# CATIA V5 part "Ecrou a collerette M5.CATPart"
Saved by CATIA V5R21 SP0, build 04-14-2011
Part number: Ecrou a collerette M5
Material "Acier": density 7860 kg/m3, Young's modulus 2e+11 Pa, Poisson ratio 0.266, thermal expansion 1.17e-05 1/K
Bounding box of the stored display mesh (mm): x -7.998 to 7.998, y -8.083 to 8.083, z 0 to 6.5
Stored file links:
  C:\Users\Olivier\Desktop\redaction CATIA (local)\pompe à moteur de ventilation refait\Ecrou a collerette M5.CATPart
  C:\Program Files\Dassault Systemes\B21\win_b64\startup\materials\French\Catalog.CATMaterial
  C:\Program Files\Dassault Systemes\B21\win_b64\resources\graphic\figures\CATIA_EnvironmentMap_Satin_512x512.jpg
  C:\Users\Olivier\Desktop\redaction CATIA (local)\pompe à moteur de ventilation refait\Pompe_a_moteur_de_ventilation.CATProduct
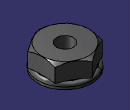
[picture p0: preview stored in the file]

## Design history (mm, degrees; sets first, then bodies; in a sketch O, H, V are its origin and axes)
Body1 (main body), material "Acier"
  Sketch1 on yz-plane, origin (0, 0, 0), H (0, 1, 0), V (0, 0, 1)
    line L1 (2.5, 0) -> (8, 0)
    line L2 (8, 0) -> (8, 0.7158)
    line L3 (7.1592, 1.703) -> (4.8411, 2.0768)
    line L4 (4.8411, 2.0768) -> (4.8411, 6.5)
    line L5 (2.5, 0) -> (2.5, 6.5)
    arc A1 centre (7, 0.7158) radius 1 from (7.1592, 1.703) to (8, 0.7158) cw
    line L6 (4.8411, 6.5) -> (2.5, 6.5)
    distance L5 V = 2.5
    radius A1 = 1
    distance L2 V = 8
    distance L6 L1 = 6.5
    horizontal: L1 H, L6 H
    vertical: L2 V, L4 V, L5 V
    tangency: A1 L3, A1 L2
    coincidence: L1 H
  Shaft1: profile Sketch1, axis Sketch1.V, angle 360
  Sketch2 on face of Shaft1 from Sketch1.L6, origin (0, 0, 6.5), H (1, 0, 0), V (0, 1, 0)
    point P1 (7, -4.0415)
    point P2 (7, 4.0415)
    point P3 (0, 8.0829)
    point P4 (-7, 4.0415)
    point P5 (-7, -4.0415)
    point P6 (0, -8.0829)
    point P7 (7, 0)
    line L1 (7, -4.0415) -> (7, 4.0415)
    line L2 (7, 4.0415) -> (0, 8.0829)
    line L3 (0, 8.0829) -> (-7, 4.0415)
    line L4 (-7, 4.0415) -> (-7, -4.0415)
    line L5 (-7, -4.0415) -> (0, -8.0829)
    line L6 (0, -8.0829) -> (7, -4.0415)
    construction line L7 (0, 0) -> (7, 0)
    construction circle A1 centre (0, 0) radius 8.0829
    construction arc A2 centre (-7, -4.0415) radius 8.0829 from (-7, 4.0415) to (0, -8.0829) cw
    construction arc A3 centre (7, 4.0415) radius 8.0829 from (0, 8.0829) to (7, -4.0415) ccw
    circle A4 centre (0, 0) radius 2.5
    distance L1 L4 = 14
    radius A4 = 2.5
    horizontal: L7 H
    coincidence: A1 P1, A1 P2, A1 P3, A1 P4, A1 P5, A1 P6, A2 O, A3 O
    midpoint: P7 L1
    parallelism: L1 L4
  Pad1: profile Sketch2, direction (0, 0, -1), length 5
  Sketch3 on yz-plane, origin (0, 0, 0), H (0, 1, 0), V (0, 0, 1)
    reference projected line E1 (8.0829, 6.5) -> (8.0829, 1.5) from edge [face of Pad1 from Sketch2.L2 | face of Pad1 from Sketch2.L3]
    reference projected line E2 (4.0415, 6.5) -> (8.0829, 6.5) from edge [face of Pad1 from Sketch2.L2 | face of Pad1]
    line L1 (6.9488, 6.5) -> (8.0829, 5.5757)
    point P5 (6.9488, 6.5)
    point P6 (8.0829, 5.5757)
    line L2 (8.0829, 5.5757) -> (8.0829, 6.5)
    line L3 (8.0829, 6.5) -> (6.9488, 6.5)
    point P7 (6.9488, 6.5)
    coincidence: P5 E2, P6 E1, P7 L1, P5 P7
    vertical: L2 V
    horizontal: L3 H
  Groove1: profile Sketch3, axis axis of face of Pad1, angle 360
